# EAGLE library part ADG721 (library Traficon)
Dual spst analog switch Farnell 942-5764
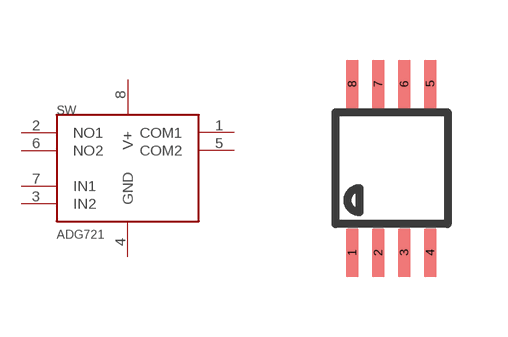
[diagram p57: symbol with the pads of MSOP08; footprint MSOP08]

Designator prefix SW

## ADG721  [MSOP08]
1  COM1
2  NO1
3  IN2
4  GND
5  COM2
6  NO2
7  IN1
8  V+

## Footprint MSOP08 (pad centres in mm)
Mini Small Outline Package Grid 0.5mm
smd 0.3 x 1.2: 1 -0.976,-2.113; 2 -0.326,-2.113; 3 0.324,-2.113; 4 0.974,-2.113; 5 0.974,2.112; 6 0.324,2.112; 7 -0.326,2.112; 8 -0.976,2.112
